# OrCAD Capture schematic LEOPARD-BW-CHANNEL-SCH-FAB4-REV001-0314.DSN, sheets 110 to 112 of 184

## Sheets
110 061_DDR4 DIMM CPU1 CHE-2: size A3; title: DDR4 DIMM CPU1 CHE-2
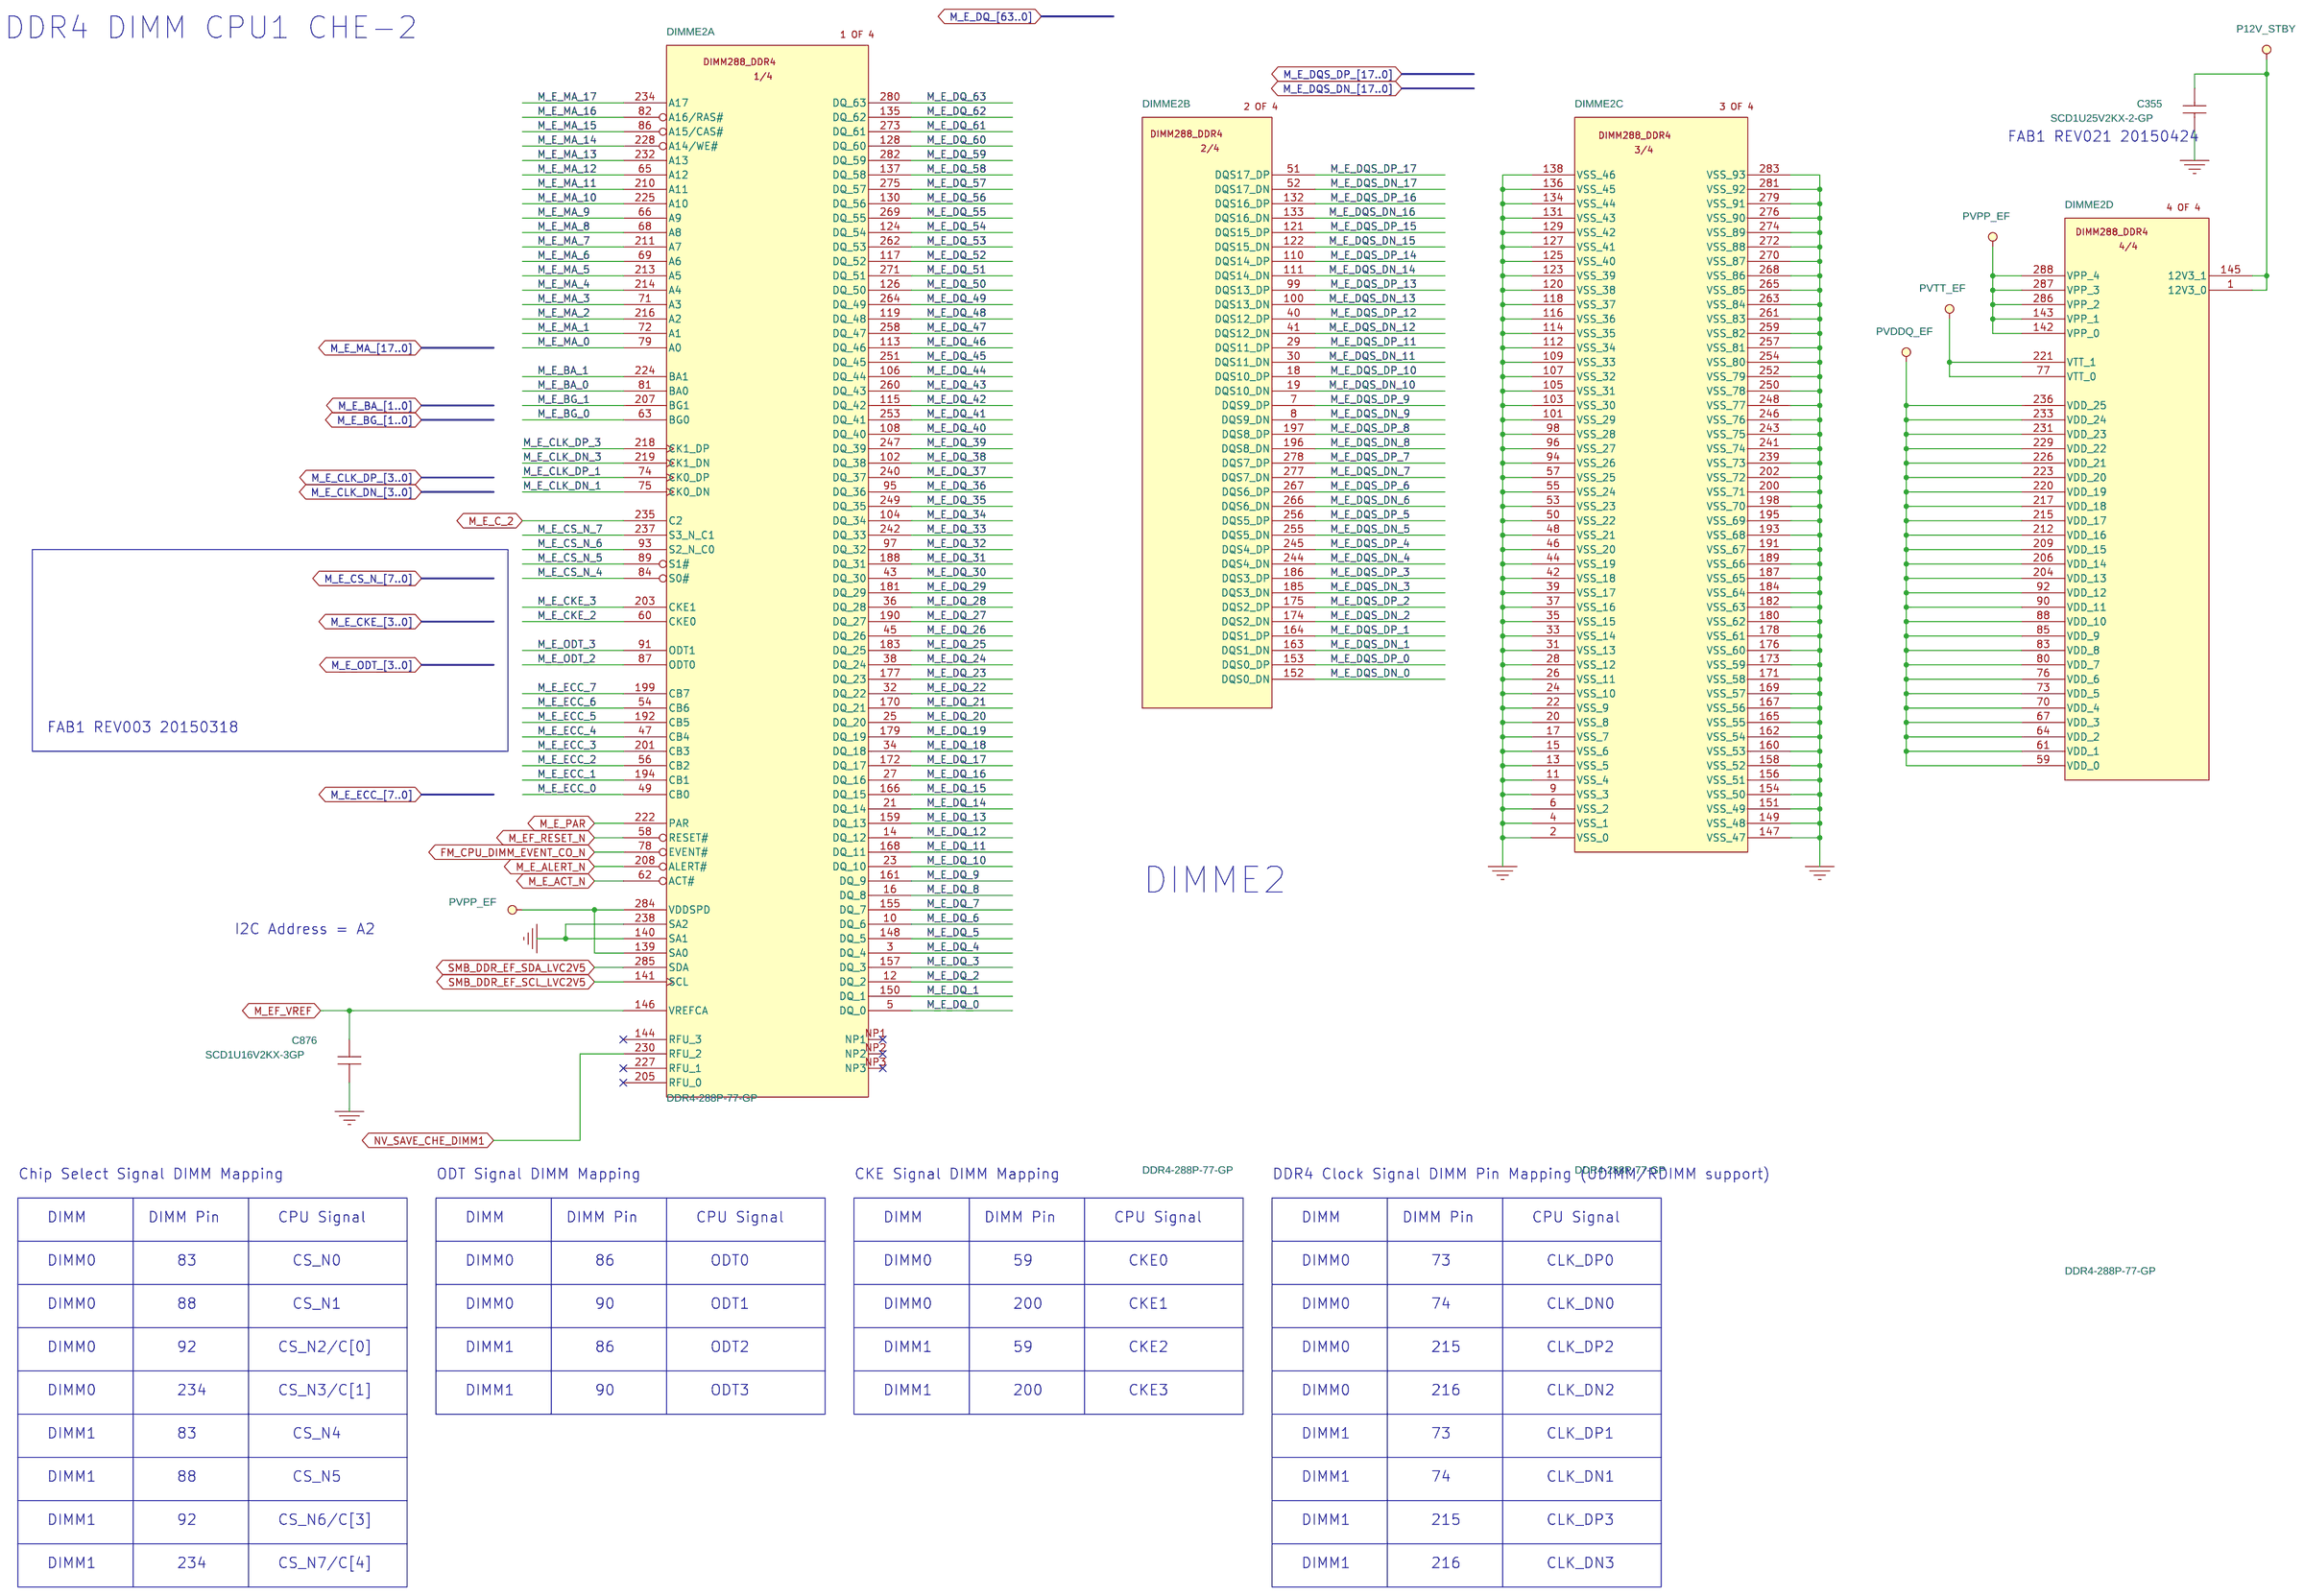
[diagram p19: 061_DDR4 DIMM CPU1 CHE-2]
111 060_DDR4 DIMM CPU1 CHE-1: size A3; title: DDR4 DIMM CPU1 CHE-1
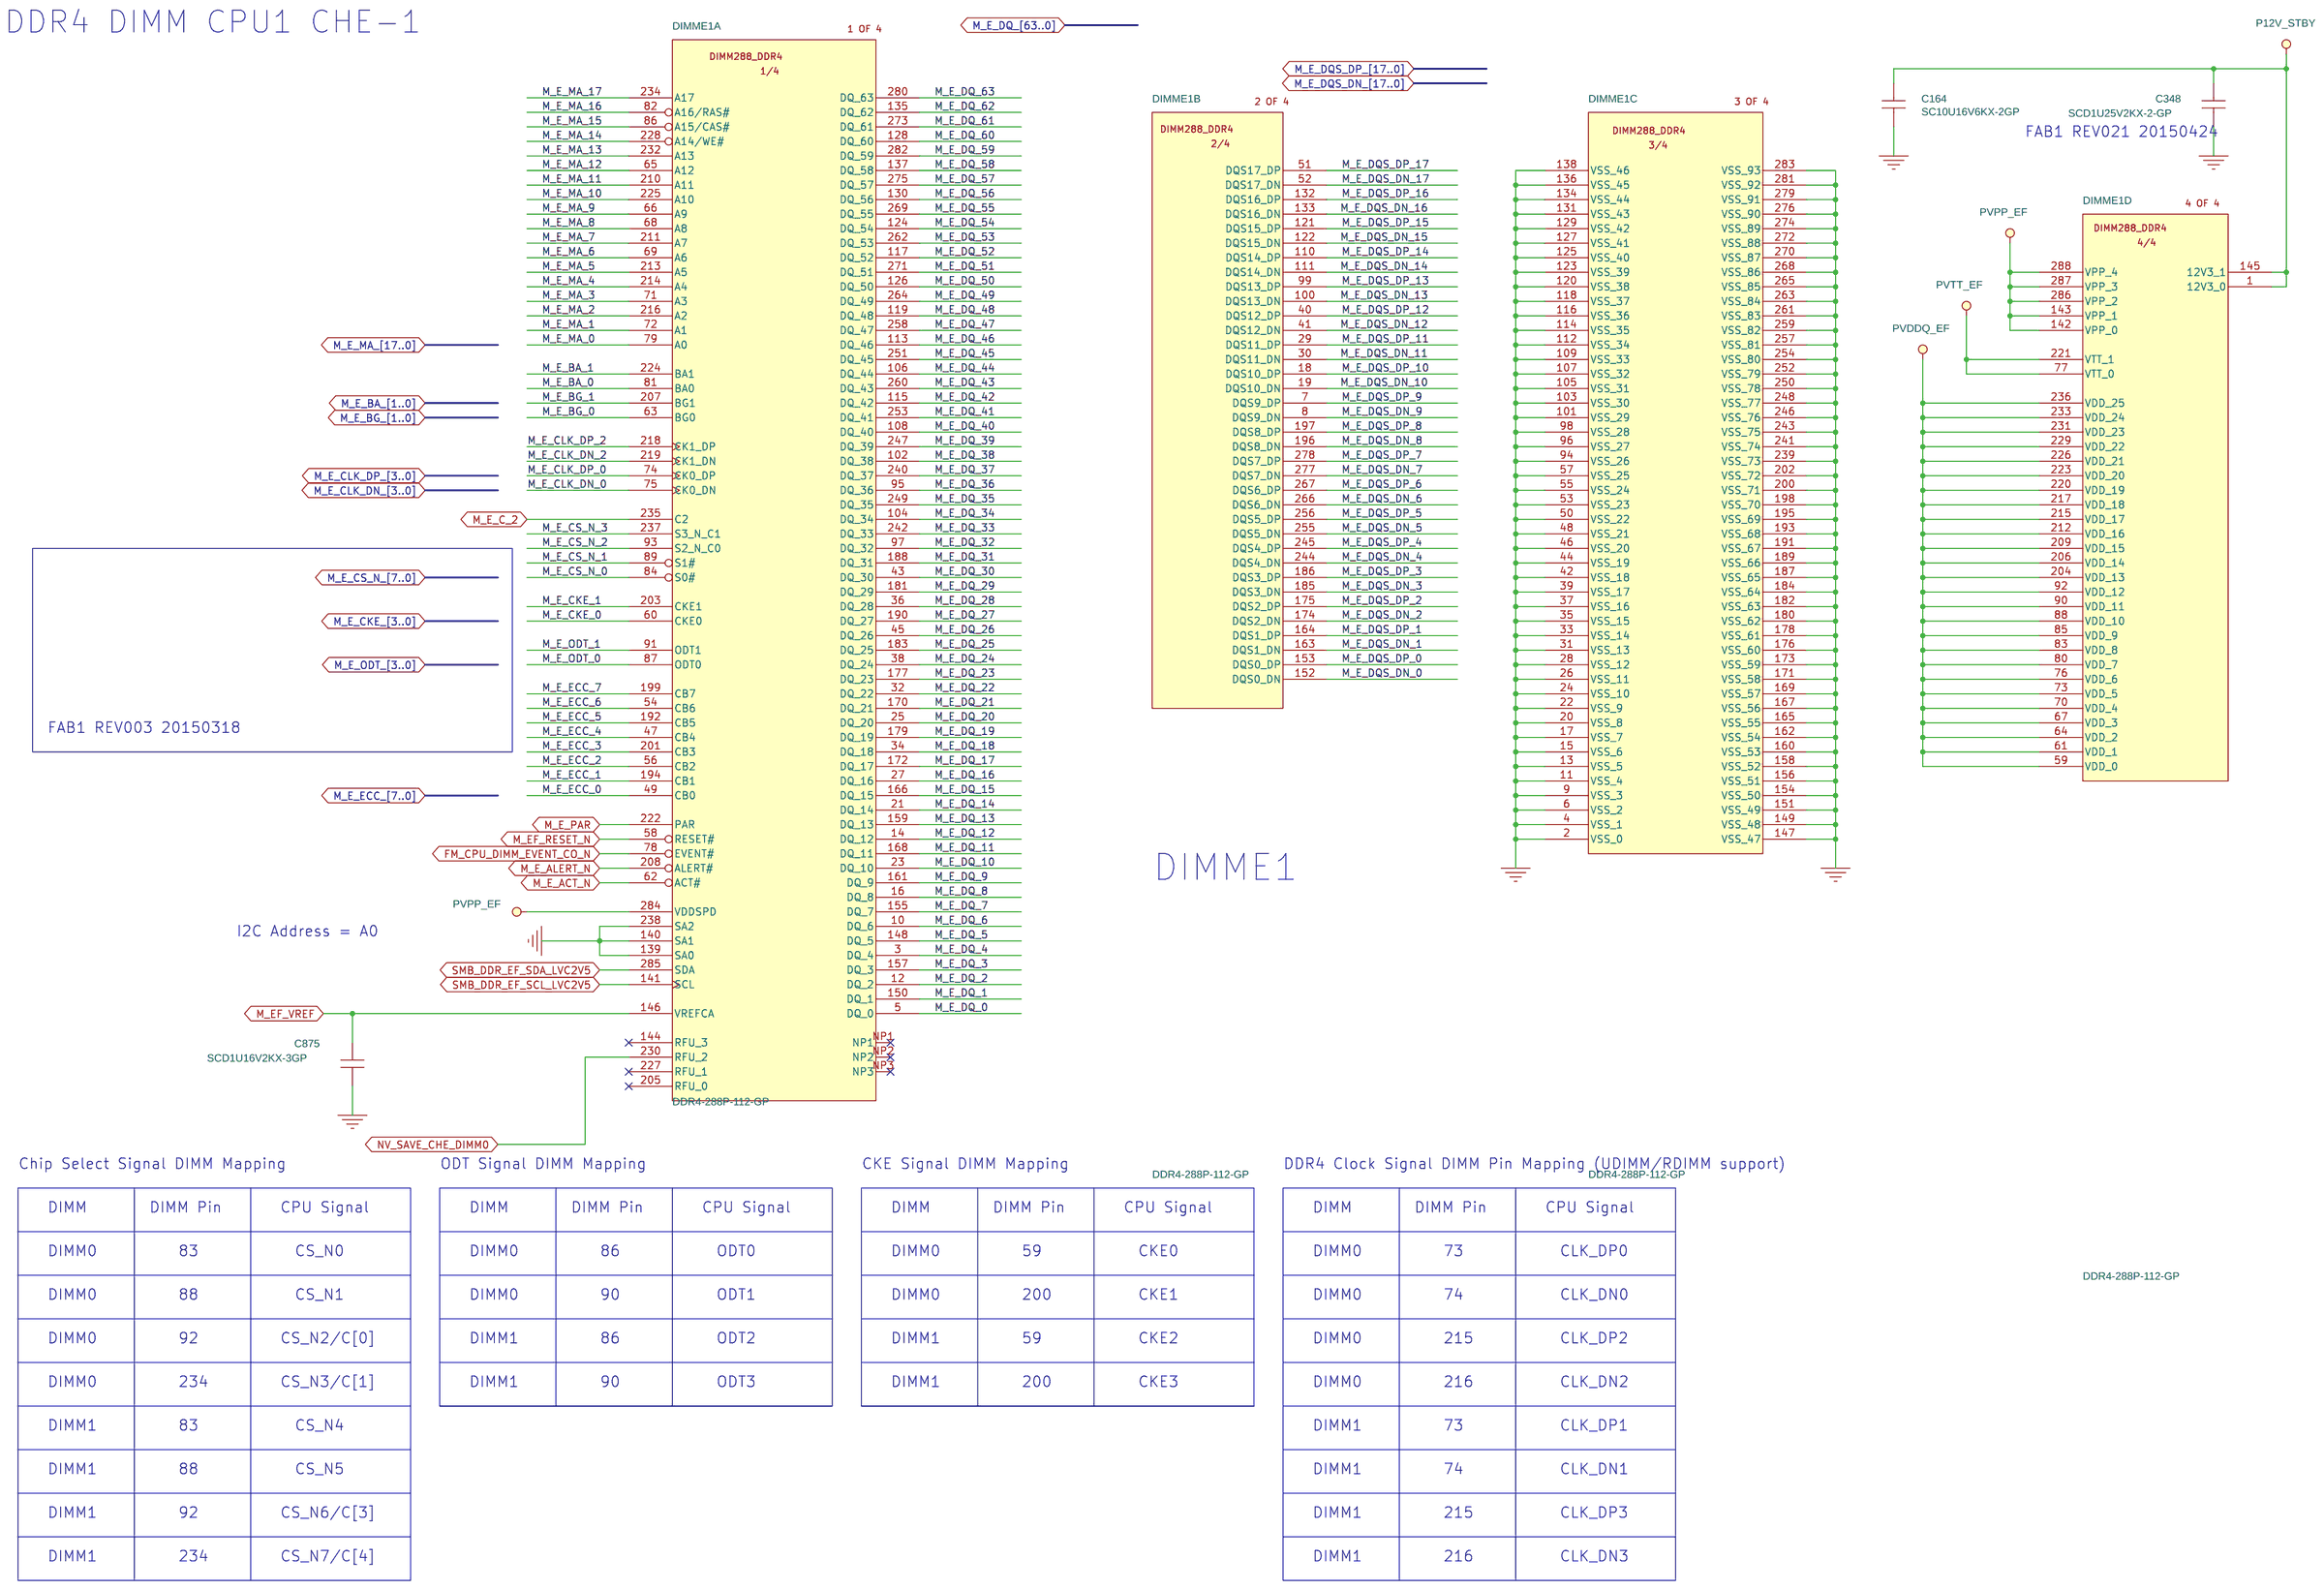
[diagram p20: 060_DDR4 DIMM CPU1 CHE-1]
112 059_DDR4 DIMM CPU0 CHD-2: size A3; title: DDR4 DIMM CPU0 CHD-2
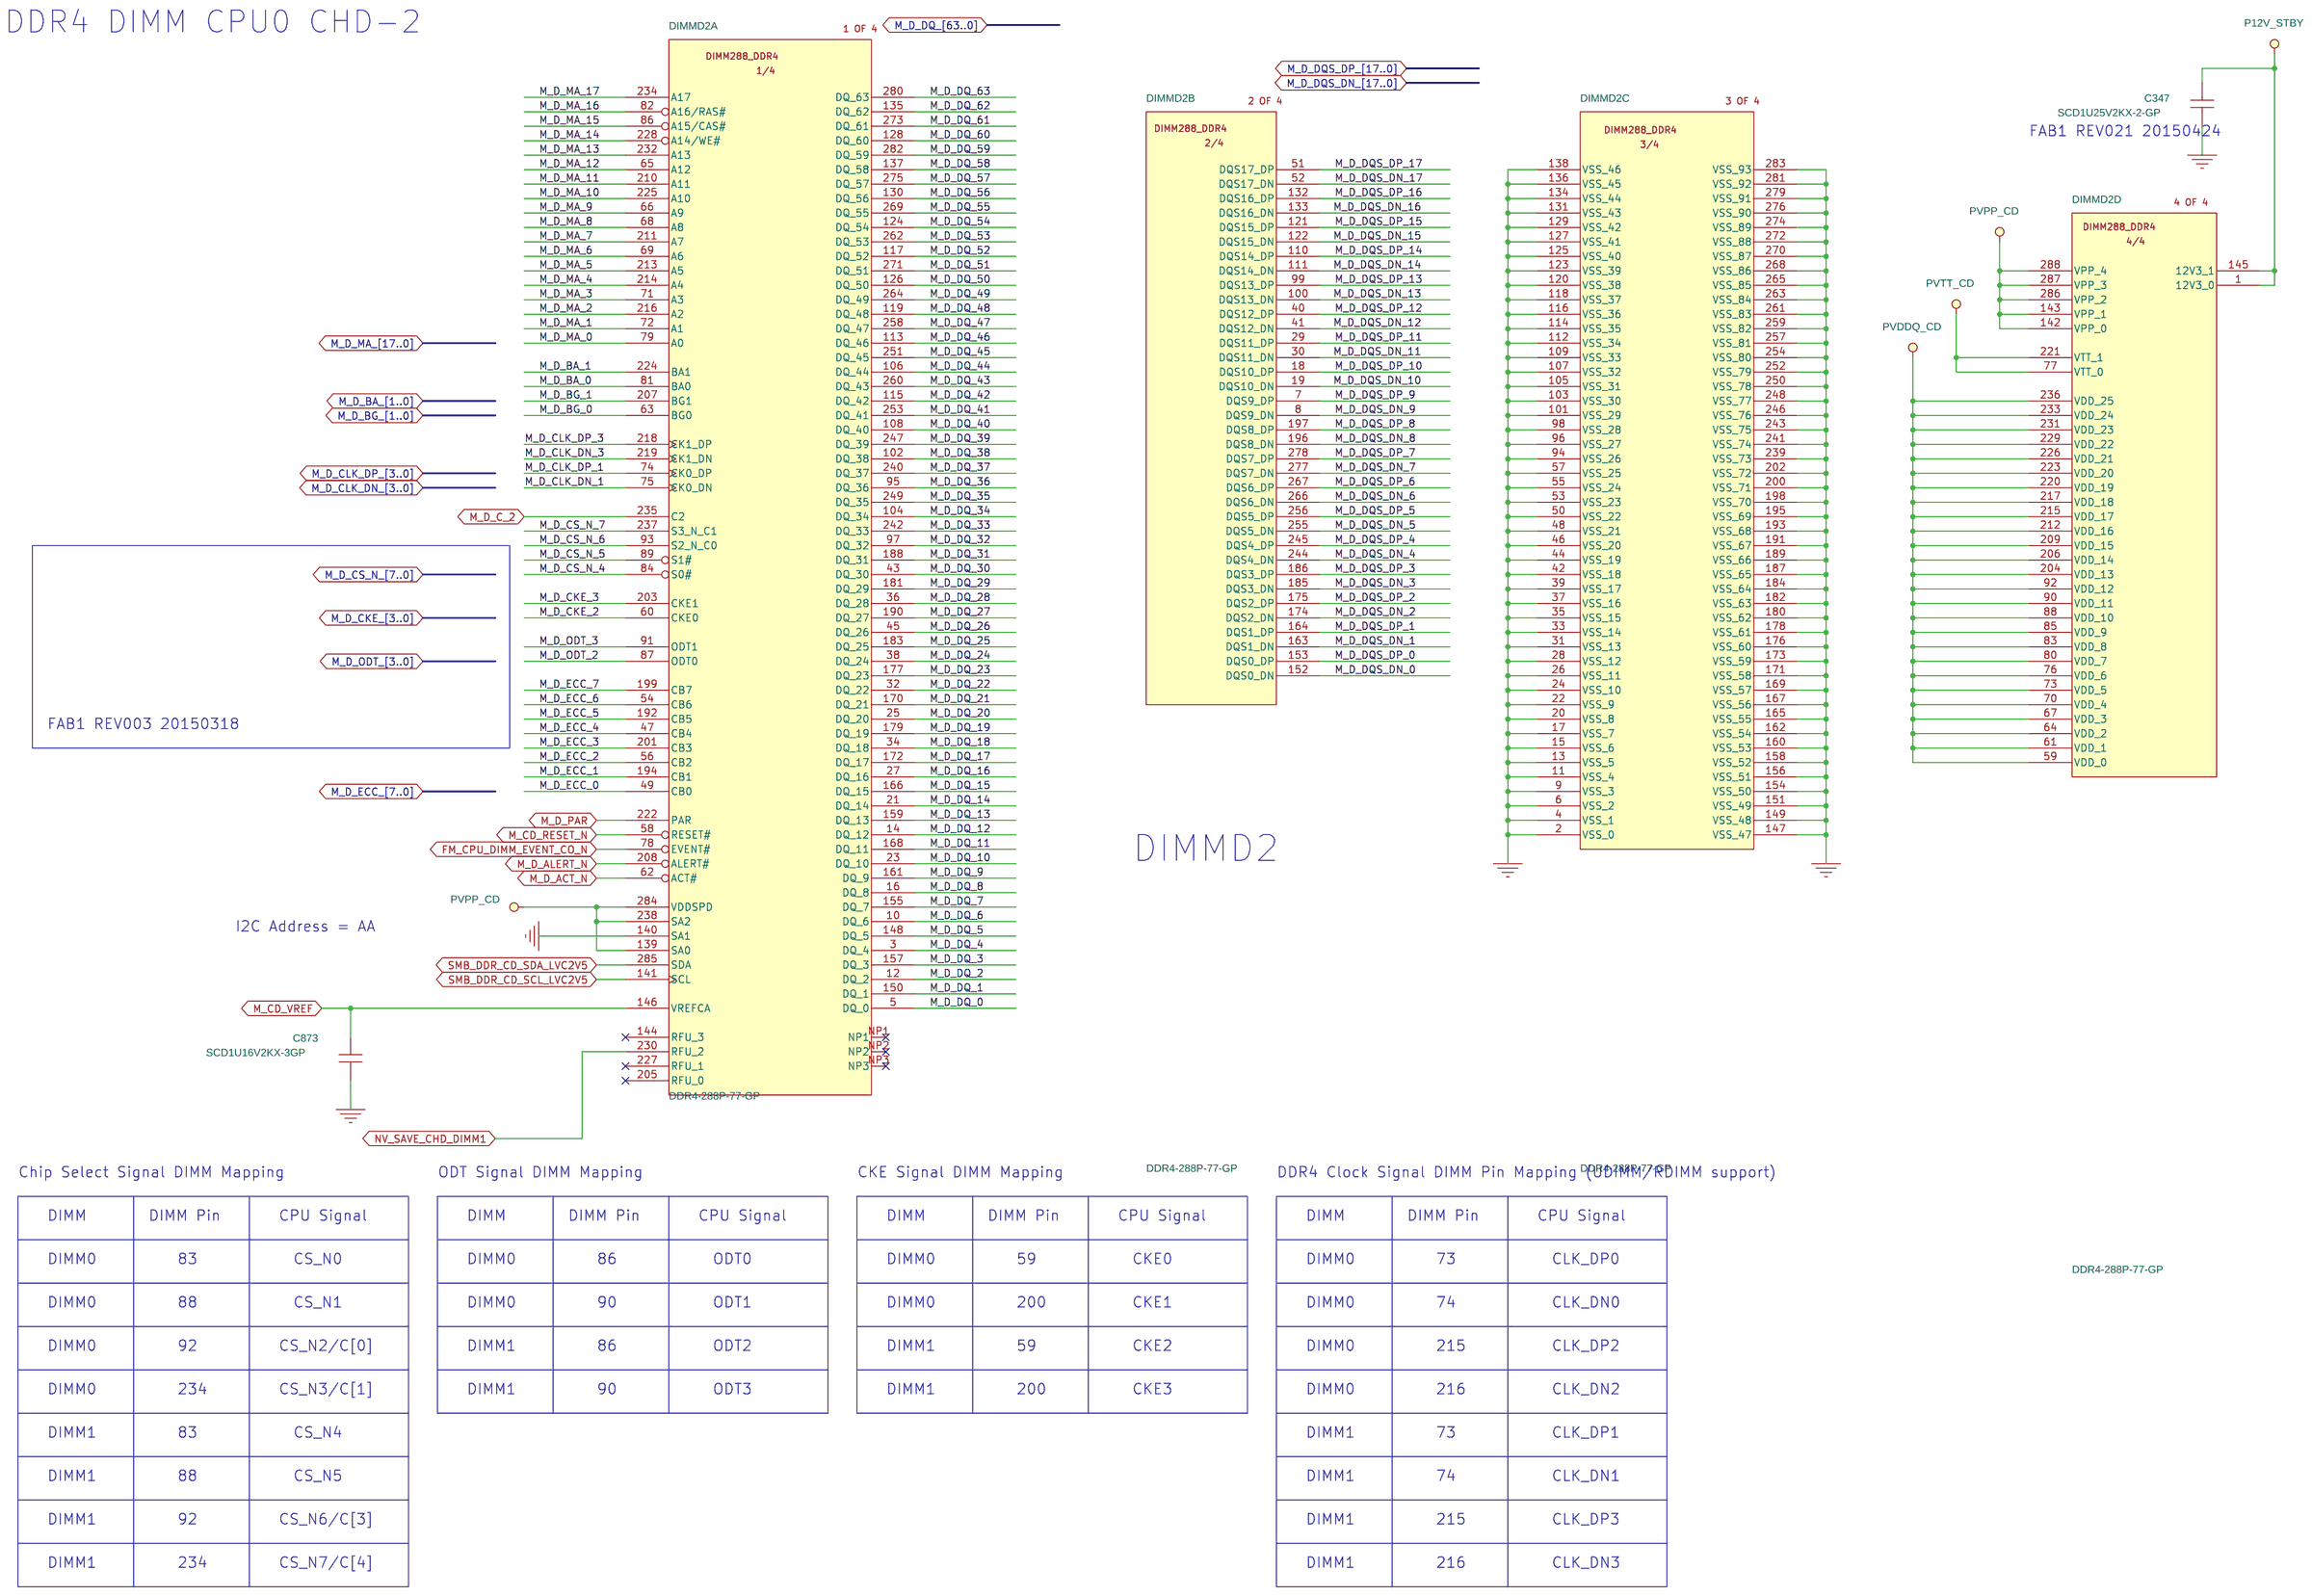
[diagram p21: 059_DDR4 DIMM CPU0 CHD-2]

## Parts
sheet 059_DDR4 DIMM CPU0 CHD-2
C347  SCD1U25V2KX-2-GP  [C402H22]
C873  SCD1U16V2KX-3GP  [C402H22]
DIMMD2  DDR4-288P-77-GP  [10124632-0001113LF]  (sections A,B,C,D)
sheet 060_DDR4 DIMM CPU1 CHE-1
C164  SC10U16V6KX-2GP  [C1206H71]
C348  SCD1U25V2KX-2-GP  [C402H22]
C875  SCD1U16V2KX-3GP  [C402H22]
DIMME1  DDR4-288P-112-GP  [10124632-0001113LF]  (sections A,B,C,D)
sheet 061_DDR4 DIMM CPU1 CHE-2
C355  SCD1U25V2KX-2-GP  [C402H22]
C876  SCD1U16V2KX-3GP  [C402H22]
DIMME2  DDR4-288P-77-GP  [10124632-0001113LF]  (sections A,B,C,D)

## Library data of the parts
C347 C348 C355 = SCD1U25V2KX-2-GP: CHIP CAP C 0.1U 25V K0402 X7R; GREENDFACTOR: R2_SA;HF_SA;G_SA;; Part Number: 78.10422.2FL; Part Type: SMD-BCG4; SPEC: http://wpqssvr.wistron.com.tw:7001/wpqs/servlet/COM.qpart.Attachment?PartNumber=78.10422.2FL
C873 C875 C876 = SCD1U16V2KX-3GP: CHIP CAP C 0.1U 16V K0402 X7R; CATEGORIES: CAP_1.xV; GREENDFACTOR: R2_SA;HF_SA;G_SA;; MAIN_SOURCE: M; Part Number: 78.10421.2FL; Part Type: SMD-BCG; SPEC: http://wpqssvr.wistron.com.tw:7001/wpqs/servlet/COM.qpart.Attachment?PartNumber=78.10421.2FL
DIMMD2 DIMME2 = DDR4-288P-77-GP: SKT DIMM DDR4 288P 10124632-0001001LF; GREENDFACTOR: R2_SA;; POP?: 022.10010.0B11; Part Number: 22.10244.1A1; Part Type: SOCKET-G1; SPEC: http://wpqssvr.wistron.com.tw:7001/wpqs/servlet/COM.qpart.Attachment?PartNumber=22.10244.1A1
C164 = SC10U16V6KX-2GP: CHIP CAP C 10U 16V K1206 X7R; GREENDFACTOR: R2_SA;HF_SA;G_SA;; Part Number: 78.10621.22L; Part Type: SMD-BCG; SPEC: http://wpqssvr.wistron.com.tw:7001/wpqs/servlet/COM.qpart.Attachment?PartNumber=78.10621.22L
DIMME1 = DDR4-288P-112-GP: SKT DIMM DDR4 288P 10124632-0003001LF; GREENDFACTOR: R2_C;; POP?: 022.10010.0E11; Part Number: 022.10010.0B91; Part Type: SOCKET-G2; SPEC: http://wpqssvr.wistron.com.tw:7001/wpqs/servlet/COM.qpart.Attachment?PartNumber=022.10010.0B91

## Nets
GND: C164.2 C347.2 C348.2 C355.2 C873.2 C875.2 C876.2 DIMMD2.2(VSS_0) DIMMD2.4(VSS_1) DIMMD2.6(VSS_2) DIMMD2.9(VSS_3) DIMMD2.11(VSS_4) DIMMD2.13(VSS_5) DIMMD2.15(VSS_6) DIMMD2.17(VSS_7) DIMMD2.20(VSS_8) DIMMD2.22(VSS_9) DIMMD2.24(VSS_10) DIMMD2.26(VSS_11) DIMMD2.28(VSS_12) DIMMD2.31(VSS_13) DIMMD2.33(VSS_14) DIMMD2.35(VSS_15) DIMMD2.37(VSS_16) DIMMD2.39(VSS_17) DIMMD2.42(VSS_18) DIMMD2.44(VSS_19) DIMMD2.46(VSS_20) DIMMD2.48(VSS_21) DIMMD2.50(VSS_22) DIMMD2.53(VSS_23) DIMMD2.55(VSS_24) DIMMD2.57(VSS_25) DIMMD2.94(VSS_26) DIMMD2.96(VSS_27) DIMMD2.98(VSS_28) DIMMD2.101(VSS_29) DIMMD2.103(VSS_30) DIMMD2.105(VSS_31) DIMMD2.107(VSS_32) DIMMD2.109(VSS_33) DIMMD2.112(VSS_34) DIMMD2.114(VSS_35) DIMMD2.116(VSS_36) DIMMD2.118(VSS_37) DIMMD2.120(VSS_38) DIMMD2.123(VSS_39) DIMMD2.125(VSS_40) DIMMD2.127(VSS_41) DIMMD2.129(VSS_42) DIMMD2.131(VSS_43) DIMMD2.134(VSS_44) DIMMD2.136(VSS_45) DIMMD2.138(VSS_46) DIMMD2.140(SA1) DIMMD2.147(VSS_47) DIMMD2.149(VSS_48) DIMMD2.151(VSS_49) DIMMD2.154(VSS_50) DIMMD2.156(VSS_51) DIMMD2.158(VSS_52) DIMMD2.160(VSS_53) DIMMD2.162(VSS_54) DIMMD2.165(VSS_55) DIMMD2.167(VSS_56) DIMMD2.169(VSS_57) DIMMD2.171(VSS_58) DIMMD2.173(VSS_59) DIMMD2.176(VSS_60) DIMMD2.178(VSS_61) DIMMD2.180(VSS_62) DIMMD2.182(VSS_63) DIMMD2.184(VSS_64) DIMMD2.187(VSS_65) DIMMD2.189(VSS_66) DIMMD2.191(VSS_67) DIMMD2.193(VSS_68) DIMMD2.195(VSS_69) DIMMD2.198(VSS_70) DIMMD2.200(VSS_71) DIMMD2.202(VSS_72) DIMMD2.239(VSS_73) DIMMD2.241(VSS_74) DIMMD2.243(VSS_75) DIMMD2.246(VSS_76) DIMMD2.248(VSS_77) DIMMD2.250(VSS_78) DIMMD2.252(VSS_79) DIMMD2.254(VSS_80) DIMMD2.257(VSS_81) DIMMD2.259(VSS_82) DIMMD2.261(VSS_83) DIMMD2.263(VSS_84) DIMMD2.265(VSS_85) DIMMD2.268(VSS_86) DIMMD2.270(VSS_87) DIMMD2.272(VSS_88) DIMMD2.274(VSS_89) DIMMD2.276(VSS_90) DIMMD2.279(VSS_91) DIMMD2.281(VSS_92) DIMMD2.283(VSS_93) DIMME1.2(VSS_0) DIMME1.4(VSS_1) DIMME1.6(VSS_2) DIMME1.9(VSS_3) DIMME1.11(VSS_4) DIMME1.13(VSS_5) DIMME1.15(VSS_6) DIMME1.17(VSS_7) DIMME1.20(VSS_8) DIMME1.22(VSS_9) DIMME1.24(VSS_10) DIMME1.26(VSS_11) DIMME1.28(VSS_12) DIMME1.31(VSS_13) DIMME1.33(VSS_14) DIMME1.35(VSS_15) DIMME1.37(VSS_16) DIMME1.39(VSS_17) DIMME1.42(VSS_18) DIMME1.44(VSS_19) DIMME1.46(VSS_20) DIMME1.48(VSS_21) DIMME1.50(VSS_22) DIMME1.53(VSS_23) DIMME1.55(VSS_24) DIMME1.57(VSS_25) DIMME1.94(VSS_26) DIMME1.96(VSS_27) DIMME1.98(VSS_28) DIMME1.101(VSS_29) DIMME1.103(VSS_30) DIMME1.105(VSS_31) DIMME1.107(VSS_32) DIMME1.109(VSS_33) DIMME1.112(VSS_34) DIMME1.114(VSS_35) DIMME1.116(VSS_36) DIMME1.118(VSS_37) DIMME1.120(VSS_38) DIMME1.123(VSS_39) DIMME1.125(VSS_40) DIMME1.127(VSS_41) DIMME1.129(VSS_42) DIMME1.131(VSS_43) DIMME1.134(VSS_44) DIMME1.136(VSS_45) DIMME1.138(VSS_46) DIMME1.139(SA0) DIMME1.140(SA1) DIMME1.147(VSS_47) DIMME1.149(VSS_48) DIMME1.151(VSS_49) DIMME1.154(VSS_50) DIMME1.156(VSS_51) DIMME1.158(VSS_52) DIMME1.160(VSS_53) DIMME1.162(VSS_54) DIMME1.165(VSS_55) DIMME1.167(VSS_56) DIMME1.169(VSS_57) DIMME1.171(VSS_58) DIMME1.173(VSS_59) DIMME1.176(VSS_60) DIMME1.178(VSS_61) DIMME1.180(VSS_62) DIMME1.182(VSS_63) DIMME1.184(VSS_64) DIMME1.187(VSS_65) DIMME1.189(VSS_66) DIMME1.191(VSS_67) DIMME1.193(VSS_68) DIMME1.195(VSS_69) DIMME1.198(VSS_70) DIMME1.200(VSS_71) DIMME1.202(VSS_72) DIMME1.238(SA2) DIMME1.239(VSS_73) DIMME1.241(VSS_74) DIMME1.243(VSS_75) DIMME1.246(VSS_76) DIMME1.248(VSS_77) DIMME1.250(VSS_78) DIMME1.252(VSS_79) DIMME1.254(VSS_80) DIMME1.257(VSS_81) DIMME1.259(VSS_82) DIMME1.261(VSS_83) DIMME1.263(VSS_84) DIMME1.265(VSS_85) DIMME1.268(VSS_86) DIMME1.270(VSS_87) DIMME1.272(VSS_88) DIMME1.274(VSS_89) DIMME1.276(VSS_90) DIMME1.279(VSS_91) DIMME1.281(VSS_92) DIMME1.283(VSS_93) DIMME2.2(VSS_0) DIMME2.4(VSS_1) DIMME2.6(VSS_2) DIMME2.9(VSS_3) DIMME2.11(VSS_4) DIMME2.13(VSS_5) DIMME2.15(VSS_6) DIMME2.17(VSS_7) DIMME2.20(VSS_8) DIMME2.22(VSS_9) DIMME2.24(VSS_10) DIMME2.26(VSS_11) DIMME2.28(VSS_12) DIMME2.31(VSS_13) DIMME2.33(VSS_14) DIMME2.35(VSS_15) DIMME2.37(VSS_16) DIMME2.39(VSS_17) DIMME2.42(VSS_18) DIMME2.44(VSS_19) DIMME2.46(VSS_20) DIMME2.48(VSS_21) DIMME2.50(VSS_22) DIMME2.53(VSS_23) DIMME2.55(VSS_24) DIMME2.57(VSS_25) DIMME2.94(VSS_26) DIMME2.96(VSS_27) DIMME2.98(VSS_28) DIMME2.101(VSS_29) DIMME2.103(VSS_30) DIMME2.105(VSS_31) DIMME2.107(VSS_32) DIMME2.109(VSS_33) DIMME2.112(VSS_34) DIMME2.114(VSS_35) DIMME2.116(VSS_36) DIMME2.118(VSS_37) DIMME2.120(VSS_38) DIMME2.123(VSS_39) DIMME2.125(VSS_40) DIMME2.127(VSS_41) DIMME2.129(VSS_42) DIMME2.131(VSS_43) DIMME2.134(VSS_44) DIMME2.136(VSS_45) DIMME2.138(VSS_46) DIMME2.140(SA1) DIMME2.147(VSS_47) DIMME2.149(VSS_48) DIMME2.151(VSS_49) DIMME2.154(VSS_50) DIMME2.156(VSS_51) DIMME2.158(VSS_52) DIMME2.160(VSS_53) DIMME2.162(VSS_54) DIMME2.165(VSS_55) DIMME2.167(VSS_56) DIMME2.169(VSS_57) DIMME2.171(VSS_58) DIMME2.173(VSS_59) DIMME2.176(VSS_60) DIMME2.178(VSS_61) DIMME2.180(VSS_62) DIMME2.182(VSS_63) DIMME2.184(VSS_64) DIMME2.187(VSS_65) DIMME2.189(VSS_66) DIMME2.191(VSS_67) DIMME2.193(VSS_68) DIMME2.195(VSS_69) DIMME2.198(VSS_70) DIMME2.200(VSS_71) DIMME2.202(VSS_72) DIMME2.238(SA2) DIMME2.239(VSS_73) DIMME2.241(VSS_74) DIMME2.243(VSS_75) DIMME2.246(VSS_76) DIMME2.248(VSS_77) DIMME2.250(VSS_78) DIMME2.252(VSS_79) DIMME2.254(VSS_80) DIMME2.257(VSS_81) DIMME2.259(VSS_82) DIMME2.261(VSS_83) DIMME2.263(VSS_84) DIMME2.265(VSS_85) DIMME2.268(VSS_86) DIMME2.270(VSS_87) DIMME2.272(VSS_88) DIMME2.274(VSS_89) DIMME2.276(VSS_90) DIMME2.279(VSS_91) DIMME2.281(VSS_92) DIMME2.283(VSS_93) ; also on sheet 1 2 3 4 5 6 7 8 9 10 11 12 13 14 15 16 17 18 19 20 21 22 23 24 25 26 27 28 29 30 31 32 33 34 35 36 37 38 39 44 46 47 49 50 51 52 53 54 55 56 57 58 59 60 61 62 63 64 65 66 69 70 71 73 74 75 76 78 79 80 81 82 83 84 86 87 88 89 90 91 92 93 94 95 96 97 98 99 100 101 102 103 104 105 106 107 108 109 113 114 115 116 117 118 119 128 129 138 139 159 160 161 166 168 169 170 171 172 173 174 175 176 177 180 181 182 183 184
P12V_STBY: C164.1 C347.1 C348.1 C355.1 DIMMD2.1(12V3_0) DIMMD2.145(12V3_1) DIMME1.1(12V3_0) DIMME1.145(12V3_1) DIMME2.1(12V3_0) DIMME2.145(12V3_1) ; also on sheet 2 3 4 7 9 10 11 12 13 17 18 22 23 27 28 32 36 59 60 75 95 104 105 106 107 108 109 113 114 115 116 117 118 119
PVDDQ_CD: DIMMD2.59(VDD_0) DIMMD2.61(VDD_1) DIMMD2.64(VDD_2) DIMMD2.67(VDD_3) DIMMD2.70(VDD_4) DIMMD2.73(VDD_5) DIMMD2.76(VDD_6) DIMMD2.80(VDD_7) DIMMD2.83(VDD_8) DIMMD2.85(VDD_9) DIMMD2.88(VDD_10) DIMMD2.90(VDD_11) DIMMD2.92(VDD_12) DIMMD2.204(VDD_13) DIMMD2.206(VDD_14) DIMMD2.209(VDD_15) DIMMD2.212(VDD_16) DIMMD2.215(VDD_17) DIMMD2.217(VDD_18) DIMMD2.220(VDD_19) DIMMD2.223(VDD_20) DIMMD2.226(VDD_21) DIMMD2.229(VDD_22) DIMMD2.231(VDD_23) DIMMD2.233(VDD_24) DIMMD2.236(VDD_25) ; also on sheet 23 25 45 97 113 114 115 130 139
PVDDQ_EF: DIMME1.59(VDD_0) DIMME1.61(VDD_1) DIMME1.64(VDD_2) DIMME1.67(VDD_3) DIMME1.70(VDD_4) DIMME1.73(VDD_5) DIMME1.76(VDD_6) DIMME1.80(VDD_7) DIMME1.83(VDD_8) DIMME1.85(VDD_9) DIMME1.88(VDD_10) DIMME1.90(VDD_11) DIMME1.92(VDD_12) DIMME1.204(VDD_13) DIMME1.206(VDD_14) DIMME1.209(VDD_15) DIMME1.212(VDD_16) DIMME1.215(VDD_17) DIMME1.217(VDD_18) DIMME1.220(VDD_19) DIMME1.223(VDD_20) DIMME1.226(VDD_21) DIMME1.229(VDD_22) DIMME1.231(VDD_23) DIMME1.233(VDD_24) DIMME1.236(VDD_25) DIMME2.59(VDD_0) DIMME2.61(VDD_1) DIMME2.64(VDD_2) DIMME2.67(VDD_3) DIMME2.70(VDD_4) DIMME2.73(VDD_5) DIMME2.76(VDD_6) DIMME2.80(VDD_7) DIMME2.83(VDD_8) DIMME2.85(VDD_9) DIMME2.88(VDD_10) DIMME2.90(VDD_11) DIMME2.92(VDD_12) DIMME2.204(VDD_13) DIMME2.206(VDD_14) DIMME2.209(VDD_15) DIMME2.212(VDD_16) DIMME2.215(VDD_17) DIMME2.217(VDD_18) DIMME2.220(VDD_19) DIMME2.223(VDD_20) DIMME2.226(VDD_21) DIMME2.229(VDD_22) DIMME2.231(VDD_23) DIMME2.233(VDD_24) DIMME2.236(VDD_25) ; also on sheet 18 20 45 97 108 109 120 129
FM_CPU_DIMM_EVENT_CO_N: DIMMD2.78(EVENT#) DIMME1.78(EVENT#) DIMME2.78(EVENT#) ; also on sheet 98 104 105 106 107 108 109 113 114 115 116 117 118 119
M_CD_RESET_N: DIMMD2.58(RESET#) ; also on sheet 113 114 115 139
M_CD_VREF: C873.1 DIMMD2.146(VREFCA) ; also on sheet 113 114 115 139
M_D_ACT_N: DIMMD2.62(ACT#) ; also on sheet 113 134
M_D_ALERT_N: DIMMD2.208(ALERT#) ; also on sheet 113 134
M_D_BA_0: DIMMD2.81(BA0) ; also on sheet 113 134
M_D_BA_1: DIMMD2.224(BA1) ; also on sheet 113 134
M_D_BG_0: DIMMD2.63(BG0) ; also on sheet 113 134
M_D_BG_1: DIMMD2.207(BG1) ; also on sheet 113 134
M_D_C_2: DIMMD2.235(C2) ; also on sheet 113 134
M_D_CKE_2: DIMMD2.60(CKE0) ; also on sheet 134
M_D_CKE_3: DIMMD2.203(CKE1) ; also on sheet 134
M_D_CLK_DN_1: DIMMD2.75(CK0_DN) ; also on sheet 134
M_D_CLK_DN_3: DIMMD2.219(CK1_DN) ; also on sheet 134
M_D_CLK_DP_1: DIMMD2.74(CK0_DP) ; also on sheet 134
M_D_CLK_DP_3: DIMMD2.218(CK1_DP) ; also on sheet 134
M_D_CS_N_4: DIMMD2.84(S0#) ; also on sheet 134
M_D_CS_N_5: DIMMD2.89(S1#) ; also on sheet 134
M_D_CS_N_6: DIMMD2.93(S2_N_C0) ; also on sheet 134
M_D_CS_N_7: DIMMD2.237(S3_N_C1) ; also on sheet 134
M_D_DQ_0: DIMMD2.5(DQ_0) ; also on sheet 113 134
M_D_DQ_1: DIMMD2.150(DQ_1) ; also on sheet 113 134
M_D_DQ_2: DIMMD2.12(DQ_2) ; also on sheet 113 134
M_D_DQ_3: DIMMD2.157(DQ_3) ; also on sheet 113 134
M_D_DQ_4: DIMMD2.3(DQ_4) ; also on sheet 113 134
M_D_DQ_5: DIMMD2.148(DQ_5) ; also on sheet 113 134
M_D_DQ_6: DIMMD2.10(DQ_6) ; also on sheet 113 134
M_D_DQ_7: DIMMD2.155(DQ_7) ; also on sheet 113 134
M_D_DQ_8: DIMMD2.16(DQ_8) ; also on sheet 113 134
M_D_DQ_9: DIMMD2.161(DQ_9) ; also on sheet 113 134
M_D_DQ_10: DIMMD2.23(DQ_10) ; also on sheet 113 134
M_D_DQ_11: DIMMD2.168(DQ_11) ; also on sheet 113 134
M_D_DQ_12: DIMMD2.14(DQ_12) ; also on sheet 113 134
M_D_DQ_13: DIMMD2.159(DQ_13) ; also on sheet 113 134
M_D_DQ_14: DIMMD2.21(DQ_14) ; also on sheet 113 134
M_D_DQ_15: DIMMD2.166(DQ_15) ; also on sheet 113 134
M_D_DQ_16: DIMMD2.27(DQ_16) ; also on sheet 113 134
M_D_DQ_17: DIMMD2.172(DQ_17) ; also on sheet 113 134
M_D_DQ_18: DIMMD2.34(DQ_18) ; also on sheet 113 134
M_D_DQ_19: DIMMD2.179(DQ_19) ; also on sheet 113 134
M_D_DQ_20: DIMMD2.25(DQ_20) ; also on sheet 113 134
M_D_DQ_21: DIMMD2.170(DQ_21) ; also on sheet 113 134
M_D_DQ_22: DIMMD2.32(DQ_22) ; also on sheet 113 134
M_D_DQ_23: DIMMD2.177(DQ_23) ; also on sheet 113 134
M_D_DQ_24: DIMMD2.38(DQ_24) ; also on sheet 113 134
M_D_DQ_25: DIMMD2.183(DQ_25) ; also on sheet 113 134
M_D_DQ_26: DIMMD2.45(DQ_26) ; also on sheet 113 134
M_D_DQ_27: DIMMD2.190(DQ_27) ; also on sheet 113 134
M_D_DQ_28: DIMMD2.36(DQ_28) ; also on sheet 113 134
M_D_DQ_29: DIMMD2.181(DQ_29) ; also on sheet 113 134
M_D_DQ_30: DIMMD2.43(DQ_30) ; also on sheet 113 134
M_D_DQ_31: DIMMD2.188(DQ_31) ; also on sheet 113 134
M_D_DQ_32: DIMMD2.97(DQ_32) ; also on sheet 113 134
M_D_DQ_33: DIMMD2.242(DQ_33) ; also on sheet 113 134
M_D_DQ_34: DIMMD2.104(DQ_34) ; also on sheet 113 134
M_D_DQ_35: DIMMD2.249(DQ_35) ; also on sheet 113 134
M_D_DQ_36: DIMMD2.95(DQ_36) ; also on sheet 113 134
M_D_DQ_37: DIMMD2.240(DQ_37) ; also on sheet 113 134
M_D_DQ_38: DIMMD2.102(DQ_38) ; also on sheet 113 134
M_D_DQ_39: DIMMD2.247(DQ_39) ; also on sheet 113 134
M_D_DQ_40: DIMMD2.108(DQ_40) ; also on sheet 113 134
M_D_DQ_41: DIMMD2.253(DQ_41) ; also on sheet 113 134
M_D_DQ_42: DIMMD2.115(DQ_42) ; also on sheet 113 134
M_D_DQ_43: DIMMD2.260(DQ_43) ; also on sheet 113 134
M_D_DQ_44: DIMMD2.106(DQ_44) ; also on sheet 113 134
M_D_DQ_45: DIMMD2.251(DQ_45) ; also on sheet 113 134
M_D_DQ_46: DIMMD2.113(DQ_46) ; also on sheet 113 134
M_D_DQ_47: DIMMD2.258(DQ_47) ; also on sheet 113 134
M_D_DQ_48: DIMMD2.119(DQ_48) ; also on sheet 113 134
M_D_DQ_49: DIMMD2.264(DQ_49) ; also on sheet 113 134
M_D_DQ_50: DIMMD2.126(DQ_50) ; also on sheet 113 134
M_D_DQ_51: DIMMD2.271(DQ_51) ; also on sheet 113 134
M_D_DQ_52: DIMMD2.117(DQ_52) ; also on sheet 113 134
M_D_DQ_53: DIMMD2.262(DQ_53) ; also on sheet 113 134
M_D_DQ_54: DIMMD2.124(DQ_54) ; also on sheet 113 134
M_D_DQ_55: DIMMD2.269(DQ_55) ; also on sheet 113 134
M_D_DQ_56: DIMMD2.130(DQ_56) ; also on sheet 113 134
M_D_DQ_57: DIMMD2.275(DQ_57) ; also on sheet 113 134
M_D_DQ_58: DIMMD2.137(DQ_58) ; also on sheet 113 134
M_D_DQ_59: DIMMD2.282(DQ_59) ; also on sheet 113 134
M_D_DQ_60: DIMMD2.128(DQ_60) ; also on sheet 113 134
M_D_DQ_61: DIMMD2.273(DQ_61) ; also on sheet 113 134
M_D_DQ_62: DIMMD2.135(DQ_62) ; also on sheet 113 134
M_D_DQ_63: DIMMD2.280(DQ_63) ; also on sheet 113 134
M_D_DQS_DN_0: DIMMD2.152(DQS0_DN) ; also on sheet 113 134
M_D_DQS_DN_1: DIMMD2.163(DQS1_DN) ; also on sheet 113 134
M_D_DQS_DN_2: DIMMD2.174(DQS2_DN) ; also on sheet 113 134
M_D_DQS_DN_3: DIMMD2.185(DQS3_DN) ; also on sheet 113 134
M_D_DQS_DN_4: DIMMD2.244(DQS4_DN) ; also on sheet 113 134
M_D_DQS_DN_5: DIMMD2.255(DQS5_DN) ; also on sheet 113 134
M_D_DQS_DN_6: DIMMD2.266(DQS6_DN) ; also on sheet 113 134
M_D_DQS_DN_7: DIMMD2.277(DQS7_DN) ; also on sheet 113 134
M_D_DQS_DN_8: DIMMD2.196(DQS8_DN) ; also on sheet 113 134
M_D_DQS_DN_9: DIMMD2.8(DQS9_DN) ; also on sheet 113 134
M_D_DQS_DN_10: DIMMD2.19(DQS10_DN) ; also on sheet 113 134
M_D_DQS_DN_11: DIMMD2.30(DQS11_DN) ; also on sheet 113 134
M_D_DQS_DN_12: DIMMD2.41(DQS12_DN) ; also on sheet 113 134
M_D_DQS_DN_13: DIMMD2.100(DQS13_DN) ; also on sheet 113 134
M_D_DQS_DN_14: DIMMD2.111(DQS14_DN) ; also on sheet 113 134
M_D_DQS_DN_15: DIMMD2.122(DQS15_DN) ; also on sheet 113 134
M_D_DQS_DN_16: DIMMD2.133(DQS16_DN) ; also on sheet 113 134
M_D_DQS_DN_17: DIMMD2.52(DQS17_DN) ; also on sheet 113 134
M_D_DQS_DP_0: DIMMD2.153(DQS0_DP) ; also on sheet 113 134
M_D_DQS_DP_1: DIMMD2.164(DQS1_DP) ; also on sheet 113 134
M_D_DQS_DP_2: DIMMD2.175(DQS2_DP) ; also on sheet 113 134
M_D_DQS_DP_3: DIMMD2.186(DQS3_DP) ; also on sheet 113 134
M_D_DQS_DP_4: DIMMD2.245(DQS4_DP) ; also on sheet 113 134
M_D_DQS_DP_5: DIMMD2.256(DQS5_DP) ; also on sheet 113 134
M_D_DQS_DP_6: DIMMD2.267(DQS6_DP) ; also on sheet 113 134
M_D_DQS_DP_7: DIMMD2.278(DQS7_DP) ; also on sheet 113 134
M_D_DQS_DP_8: DIMMD2.197(DQS8_DP) ; also on sheet 113 134
M_D_DQS_DP_9: DIMMD2.7(DQS9_DP) ; also on sheet 113 134
M_D_DQS_DP_10: DIMMD2.18(DQS10_DP) ; also on sheet 113 134
M_D_DQS_DP_11: DIMMD2.29(DQS11_DP) ; also on sheet 113 134
M_D_DQS_DP_12: DIMMD2.40(DQS12_DP) ; also on sheet 113 134
M_D_DQS_DP_13: DIMMD2.99(DQS13_DP) ; also on sheet 113 134
M_D_DQS_DP_14: DIMMD2.110(DQS14_DP) ; also on sheet 113 134
M_D_DQS_DP_15: DIMMD2.121(DQS15_DP) ; also on sheet 113 134
M_D_DQS_DP_16: DIMMD2.132(DQS16_DP) ; also on sheet 113 134
M_D_DQS_DP_17: DIMMD2.51(DQS17_DP) ; also on sheet 113 134
M_D_ECC_0: DIMMD2.49(CB0) ; also on sheet 113 134
M_D_ECC_1: DIMMD2.194(CB1) ; also on sheet 113 134
M_D_ECC_2: DIMMD2.56(CB2) ; also on sheet 113 134
M_D_ECC_3: DIMMD2.201(CB3) ; also on sheet 113 134
M_D_ECC_4: DIMMD2.47(CB4) ; also on sheet 113 134
M_D_ECC_5: DIMMD2.192(CB5) ; also on sheet 113 134
M_D_ECC_6: DIMMD2.54(CB6) ; also on sheet 113 134
M_D_ECC_7: DIMMD2.199(CB7) ; also on sheet 113 134
M_D_MA_0: DIMMD2.79(A0) ; also on sheet 113 134
M_D_MA_1: DIMMD2.72(A1) ; also on sheet 113 134
M_D_MA_2: DIMMD2.216(A2) ; also on sheet 113 134
M_D_MA_3: DIMMD2.71(A3) ; also on sheet 113 134
M_D_MA_4: DIMMD2.214(A4) ; also on sheet 113 134
M_D_MA_5: DIMMD2.213(A5) ; also on sheet 113 134
M_D_MA_6: DIMMD2.69(A6) ; also on sheet 113 134
M_D_MA_7: DIMMD2.211(A7) ; also on sheet 113 134
M_D_MA_8: DIMMD2.68(A8) ; also on sheet 113 134
M_D_MA_9: DIMMD2.66(A9) ; also on sheet 113 134
M_D_MA_10: DIMMD2.225(A10) ; also on sheet 113 134
M_D_MA_11: DIMMD2.210(A11) ; also on sheet 113 134
M_D_MA_12: DIMMD2.65(A12) ; also on sheet 113 134
M_D_MA_13: DIMMD2.232(A13) ; also on sheet 113 134
M_D_MA_14: DIMMD2.228(A14/WE#) ; also on sheet 113 134
M_D_MA_15: DIMMD2.86(A15/CAS#) ; also on sheet 113 134
M_D_MA_16: DIMMD2.82(A16/RAS#) ; also on sheet 113 134
M_D_MA_17: DIMMD2.234(A17) ; also on sheet 113 134
M_D_ODT_2: DIMMD2.87(ODT0) ; also on sheet 134
M_D_ODT_3: DIMMD2.91(ODT1) ; also on sheet 134
M_D_PAR: DIMMD2.222(PAR) ; also on sheet 113 134
M_E_ACT_N: DIMME1.62(ACT#) DIMME2.62(ACT#) ; also on sheet 127
M_E_ALERT_N: DIMME1.208(ALERT#) DIMME2.208(ALERT#) ; also on sheet 127
M_E_BA_0: DIMME1.81(BA0) DIMME2.81(BA0) ; also on sheet 127
M_E_BA_1: DIMME1.224(BA1) DIMME2.224(BA1) ; also on sheet 127
M_E_BG_0: DIMME1.63(BG0) DIMME2.63(BG0) ; also on sheet 127
M_E_BG_1: DIMME1.207(BG1) DIMME2.207(BG1) ; also on sheet 127
M_E_C_2: DIMME1.235(C2) DIMME2.235(C2) ; also on sheet 127
M_E_CKE_0: DIMME1.60(CKE0) ; also on sheet 127
M_E_CKE_1: DIMME1.203(CKE1) ; also on sheet 127
M_E_CKE_2: DIMME2.60(CKE0) ; also on sheet 127
M_E_CKE_3: DIMME2.203(CKE1) ; also on sheet 127
M_E_CLK_DN_0: DIMME1.75(CK0_DN) ; also on sheet 127
M_E_CLK_DN_1: DIMME2.75(CK0_DN) ; also on sheet 127
M_E_CLK_DN_2: DIMME1.219(CK1_DN) ; also on sheet 127
M_E_CLK_DN_3: DIMME2.219(CK1_DN) ; also on sheet 127
M_E_CLK_DP_0: DIMME1.74(CK0_DP) ; also on sheet 127
M_E_CLK_DP_1: DIMME2.74(CK0_DP) ; also on sheet 127
M_E_CLK_DP_2: DIMME1.218(CK1_DP) ; also on sheet 127
M_E_CLK_DP_3: DIMME2.218(CK1_DP) ; also on sheet 127
M_E_CS_N_0: DIMME1.84(S0#) ; also on sheet 127
M_E_CS_N_1: DIMME1.89(S1#) ; also on sheet 127
M_E_CS_N_2: DIMME1.93(S2_N_C0) ; also on sheet 127
M_E_CS_N_3: DIMME1.237(S3_N_C1) ; also on sheet 127
M_E_CS_N_4: DIMME2.84(S0#) ; also on sheet 127
M_E_CS_N_5: DIMME2.89(S1#) ; also on sheet 127
M_E_CS_N_6: DIMME2.93(S2_N_C0) ; also on sheet 127
M_E_CS_N_7: DIMME2.237(S3_N_C1) ; also on sheet 127
M_E_DQ_0: DIMME1.5(DQ_0) DIMME2.5(DQ_0) ; also on sheet 127
M_E_DQ_1: DIMME1.150(DQ_1) DIMME2.150(DQ_1) ; also on sheet 127
M_E_DQ_2: DIMME1.12(DQ_2) DIMME2.12(DQ_2) ; also on sheet 127
M_E_DQ_3: DIMME1.157(DQ_3) DIMME2.157(DQ_3) ; also on sheet 127
M_E_DQ_4: DIMME1.3(DQ_4) DIMME2.3(DQ_4) ; also on sheet 127
M_E_DQ_5: DIMME1.148(DQ_5) DIMME2.148(DQ_5) ; also on sheet 127
M_E_DQ_6: DIMME1.10(DQ_6) DIMME2.10(DQ_6) ; also on sheet 127
M_E_DQ_7: DIMME1.155(DQ_7) DIMME2.155(DQ_7) ; also on sheet 127
M_E_DQ_8: DIMME1.16(DQ_8) DIMME2.16(DQ_8) ; also on sheet 127
M_E_DQ_9: DIMME1.161(DQ_9) DIMME2.161(DQ_9) ; also on sheet 127
M_E_DQ_10: DIMME1.23(DQ_10) DIMME2.23(DQ_10) ; also on sheet 127
M_E_DQ_11: DIMME1.168(DQ_11) DIMME2.168(DQ_11) ; also on sheet 127
M_E_DQ_12: DIMME1.14(DQ_12) DIMME2.14(DQ_12) ; also on sheet 127
M_E_DQ_13: DIMME1.159(DQ_13) DIMME2.159(DQ_13) ; also on sheet 127
M_E_DQ_14: DIMME1.21(DQ_14) DIMME2.21(DQ_14) ; also on sheet 127
M_E_DQ_15: DIMME1.166(DQ_15) DIMME2.166(DQ_15) ; also on sheet 127
M_E_DQ_16: DIMME1.27(DQ_16) DIMME2.27(DQ_16) ; also on sheet 127
M_E_DQ_17: DIMME1.172(DQ_17) DIMME2.172(DQ_17) ; also on sheet 127
M_E_DQ_18: DIMME1.34(DQ_18) DIMME2.34(DQ_18) ; also on sheet 127
M_E_DQ_19: DIMME1.179(DQ_19) DIMME2.179(DQ_19) ; also on sheet 127
M_E_DQ_20: DIMME1.25(DQ_20) DIMME2.25(DQ_20) ; also on sheet 127
M_E_DQ_21: DIMME1.170(DQ_21) DIMME2.170(DQ_21) ; also on sheet 127
M_E_DQ_22: DIMME1.32(DQ_22) DIMME2.32(DQ_22) ; also on sheet 127
M_E_DQ_23: DIMME1.177(DQ_23) DIMME2.177(DQ_23) ; also on sheet 127
M_E_DQ_24: DIMME1.38(DQ_24) DIMME2.38(DQ_24) ; also on sheet 127
M_E_DQ_25: DIMME1.183(DQ_25) DIMME2.183(DQ_25) ; also on sheet 127
M_E_DQ_26: DIMME1.45(DQ_26) DIMME2.45(DQ_26) ; also on sheet 127
M_E_DQ_27: DIMME1.190(DQ_27) DIMME2.190(DQ_27) ; also on sheet 127
M_E_DQ_28: DIMME1.36(DQ_28) DIMME2.36(DQ_28) ; also on sheet 127
M_E_DQ_29: DIMME1.181(DQ_29) DIMME2.181(DQ_29) ; also on sheet 127
M_E_DQ_30: DIMME1.43(DQ_30) DIMME2.43(DQ_30) ; also on sheet 127
M_E_DQ_31: DIMME1.188(DQ_31) DIMME2.188(DQ_31) ; also on sheet 127
M_E_DQ_32: DIMME1.97(DQ_32) DIMME2.97(DQ_32) ; also on sheet 127
M_E_DQ_33: DIMME1.242(DQ_33) DIMME2.242(DQ_33) ; also on sheet 127
M_E_DQ_34: DIMME1.104(DQ_34) DIMME2.104(DQ_34) ; also on sheet 127
M_E_DQ_35: DIMME1.249(DQ_35) DIMME2.249(DQ_35) ; also on sheet 127
M_E_DQ_36: DIMME1.95(DQ_36) DIMME2.95(DQ_36) ; also on sheet 127
M_E_DQ_37: DIMME1.240(DQ_37) DIMME2.240(DQ_37) ; also on sheet 127
M_E_DQ_38: DIMME1.102(DQ_38) DIMME2.102(DQ_38) ; also on sheet 127
M_E_DQ_39: DIMME1.247(DQ_39) DIMME2.247(DQ_39) ; also on sheet 127
M_E_DQ_40: DIMME1.108(DQ_40) DIMME2.108(DQ_40) ; also on sheet 127
M_E_DQ_41: DIMME1.253(DQ_41) DIMME2.253(DQ_41) ; also on sheet 127
M_E_DQ_42: DIMME1.115(DQ_42) DIMME2.115(DQ_42) ; also on sheet 127
M_E_DQ_43: DIMME1.260(DQ_43) DIMME2.260(DQ_43) ; also on sheet 127
M_E_DQ_44: DIMME1.106(DQ_44) DIMME2.106(DQ_44) ; also on sheet 127
M_E_DQ_45: DIMME1.251(DQ_45) DIMME2.251(DQ_45) ; also on sheet 127
M_E_DQ_46: DIMME1.113(DQ_46) DIMME2.113(DQ_46) ; also on sheet 127
M_E_DQ_47: DIMME1.258(DQ_47) DIMME2.258(DQ_47) ; also on sheet 127
M_E_DQ_48: DIMME1.119(DQ_48) DIMME2.119(DQ_48) ; also on sheet 127
M_E_DQ_49: DIMME1.264(DQ_49) DIMME2.264(DQ_49) ; also on sheet 127
M_E_DQ_50: DIMME1.126(DQ_50) DIMME2.126(DQ_50) ; also on sheet 127
M_E_DQ_51: DIMME1.271(DQ_51) DIMME2.271(DQ_51) ; also on sheet 127
M_E_DQ_52: DIMME1.117(DQ_52) DIMME2.117(DQ_52) ; also on sheet 127
M_E_DQ_53: DIMME1.262(DQ_53) DIMME2.262(DQ_53) ; also on sheet 127
M_E_DQ_54: DIMME1.124(DQ_54) DIMME2.124(DQ_54) ; also on sheet 127
M_E_DQ_55: DIMME1.269(DQ_55) DIMME2.269(DQ_55) ; also on sheet 127
M_E_DQ_56: DIMME1.130(DQ_56) DIMME2.130(DQ_56) ; also on sheet 127
M_E_DQ_57: DIMME1.275(DQ_57) DIMME2.275(DQ_57) ; also on sheet 127
M_E_DQ_58: DIMME1.137(DQ_58) DIMME2.137(DQ_58) ; also on sheet 127
M_E_DQ_59: DIMME1.282(DQ_59) DIMME2.282(DQ_59) ; also on sheet 127
M_E_DQ_60: DIMME1.128(DQ_60) DIMME2.128(DQ_60) ; also on sheet 127
M_E_DQ_61: DIMME1.273(DQ_61) DIMME2.273(DQ_61) ; also on sheet 127
M_E_DQ_62: DIMME1.135(DQ_62) DIMME2.135(DQ_62) ; also on sheet 127
M_E_DQ_63: DIMME1.280(DQ_63) DIMME2.280(DQ_63) ; also on sheet 127
M_E_DQS_DN_0: DIMME1.152(DQS0_DN) DIMME2.152(DQS0_DN) ; also on sheet 127
M_E_DQS_DN_1: DIMME1.163(DQS1_DN) DIMME2.163(DQS1_DN) ; also on sheet 127
M_E_DQS_DN_2: DIMME1.174(DQS2_DN) DIMME2.174(DQS2_DN) ; also on sheet 127
M_E_DQS_DN_3: DIMME1.185(DQS3_DN) DIMME2.185(DQS3_DN) ; also on sheet 127
M_E_DQS_DN_4: DIMME1.244(DQS4_DN) DIMME2.244(DQS4_DN) ; also on sheet 127
M_E_DQS_DN_5: DIMME1.255(DQS5_DN) DIMME2.255(DQS5_DN) ; also on sheet 127
M_E_DQS_DN_6: DIMME1.266(DQS6_DN) DIMME2.266(DQS6_DN) ; also on sheet 127
M_E_DQS_DN_7: DIMME1.277(DQS7_DN) DIMME2.277(DQS7_DN) ; also on sheet 127
M_E_DQS_DN_8: DIMME1.196(DQS8_DN) DIMME2.196(DQS8_DN) ; also on sheet 127
M_E_DQS_DN_9: DIMME1.8(DQS9_DN) DIMME2.8(DQS9_DN) ; also on sheet 127
M_E_DQS_DN_10: DIMME1.19(DQS10_DN) DIMME2.19(DQS10_DN) ; also on sheet 127
M_E_DQS_DN_11: DIMME1.30(DQS11_DN) DIMME2.30(DQS11_DN) ; also on sheet 127
M_E_DQS_DN_12: DIMME1.41(DQS12_DN) DIMME2.41(DQS12_DN) ; also on sheet 127
M_E_DQS_DN_13: DIMME1.100(DQS13_DN) DIMME2.100(DQS13_DN) ; also on sheet 127
M_E_DQS_DN_14: DIMME1.111(DQS14_DN) DIMME2.111(DQS14_DN) ; also on sheet 127
M_E_DQS_DN_15: DIMME1.122(DQS15_DN) DIMME2.122(DQS15_DN) ; also on sheet 127
M_E_DQS_DN_16: DIMME1.133(DQS16_DN) DIMME2.133(DQS16_DN) ; also on sheet 127
M_E_DQS_DN_17: DIMME1.52(DQS17_DN) DIMME2.52(DQS17_DN) ; also on sheet 127
M_E_DQS_DP_0: DIMME1.153(DQS0_DP) DIMME2.153(DQS0_DP) ; also on sheet 127
M_E_DQS_DP_1: DIMME1.164(DQS1_DP) DIMME2.164(DQS1_DP) ; also on sheet 127
M_E_DQS_DP_2: DIMME1.175(DQS2_DP) DIMME2.175(DQS2_DP) ; also on sheet 127
M_E_DQS_DP_3: DIMME1.186(DQS3_DP) DIMME2.186(DQS3_DP) ; also on sheet 127
M_E_DQS_DP_4: DIMME1.245(DQS4_DP) DIMME2.245(DQS4_DP) ; also on sheet 127
M_E_DQS_DP_5: DIMME1.256(DQS5_DP) DIMME2.256(DQS5_DP) ; also on sheet 127
M_E_DQS_DP_6: DIMME1.267(DQS6_DP) DIMME2.267(DQS6_DP) ; also on sheet 127
M_E_DQS_DP_7: DIMME1.278(DQS7_DP) DIMME2.278(DQS7_DP) ; also on sheet 127
M_E_DQS_DP_8: DIMME1.197(DQS8_DP) DIMME2.197(DQS8_DP) ; also on sheet 127
M_E_DQS_DP_9: DIMME1.7(DQS9_DP) DIMME2.7(DQS9_DP) ; also on sheet 127
M_E_DQS_DP_10: DIMME1.18(DQS10_DP) DIMME2.18(DQS10_DP) ; also on sheet 127
M_E_DQS_DP_11: DIMME1.29(DQS11_DP) DIMME2.29(DQS11_DP) ; also on sheet 127
M_E_DQS_DP_12: DIMME1.40(DQS12_DP) DIMME2.40(DQS12_DP) ; also on sheet 127
M_E_DQS_DP_13: DIMME1.99(DQS13_DP) DIMME2.99(DQS13_DP) ; also on sheet 127
M_E_DQS_DP_14: DIMME1.110(DQS14_DP) DIMME2.110(DQS14_DP) ; also on sheet 127
M_E_DQS_DP_15: DIMME1.121(DQS15_DP) DIMME2.121(DQS15_DP) ; also on sheet 127
M_E_DQS_DP_16: DIMME1.132(DQS16_DP) DIMME2.132(DQS16_DP) ; also on sheet 127
M_E_DQS_DP_17: DIMME1.51(DQS17_DP) DIMME2.51(DQS17_DP) ; also on sheet 127
M_E_ECC_0: DIMME1.49(CB0) DIMME2.49(CB0) ; also on sheet 127
M_E_ECC_1: DIMME1.194(CB1) DIMME2.194(CB1) ; also on sheet 127
M_E_ECC_2: DIMME1.56(CB2) DIMME2.56(CB2) ; also on sheet 127
M_E_ECC_3: DIMME1.201(CB3) DIMME2.201(CB3) ; also on sheet 127
M_E_ECC_4: DIMME1.47(CB4) DIMME2.47(CB4) ; also on sheet 127
M_E_ECC_5: DIMME1.192(CB5) DIMME2.192(CB5) ; also on sheet 127
M_E_ECC_6: DIMME1.54(CB6) DIMME2.54(CB6) ; also on sheet 127
M_E_ECC_7: DIMME1.199(CB7) DIMME2.199(CB7) ; also on sheet 127
M_E_MA_0: DIMME1.79(A0) DIMME2.79(A0) ; also on sheet 127
M_E_MA_1: DIMME1.72(A1) DIMME2.72(A1) ; also on sheet 127
M_E_MA_2: DIMME1.216(A2) DIMME2.216(A2) ; also on sheet 127
M_E_MA_3: DIMME1.71(A3) DIMME2.71(A3) ; also on sheet 127
M_E_MA_4: DIMME1.214(A4) DIMME2.214(A4) ; also on sheet 127
M_E_MA_5: DIMME1.213(A5) DIMME2.213(A5) ; also on sheet 127
M_E_MA_6: DIMME1.69(A6) DIMME2.69(A6) ; also on sheet 127
M_E_MA_7: DIMME1.211(A7) DIMME2.211(A7) ; also on sheet 127
M_E_MA_8: DIMME1.68(A8) DIMME2.68(A8) ; also on sheet 127
M_E_MA_9: DIMME1.66(A9) DIMME2.66(A9) ; also on sheet 127
M_E_MA_10: DIMME1.225(A10) DIMME2.225(A10) ; also on sheet 127
M_E_MA_11: DIMME1.210(A11) DIMME2.210(A11) ; also on sheet 127
M_E_MA_12: DIMME1.65(A12) DIMME2.65(A12) ; also on sheet 127
M_E_MA_13: DIMME1.232(A13) DIMME2.232(A13) ; also on sheet 127
M_E_MA_14: DIMME1.228(A14/WE#) DIMME2.228(A14/WE#) ; also on sheet 127
M_E_MA_15: DIMME1.86(A15/CAS#) DIMME2.86(A15/CAS#) ; also on sheet 127
M_E_MA_16: DIMME1.82(A16/RAS#) DIMME2.82(A16/RAS#) ; also on sheet 127
M_E_MA_17: DIMME1.234(A17) DIMME2.234(A17) ; also on sheet 127
M_E_ODT_0: DIMME1.87(ODT0) ; also on sheet 127
M_E_ODT_1: DIMME1.91(ODT1) ; also on sheet 127
M_E_ODT_2: DIMME2.87(ODT0) ; also on sheet 127
M_E_ODT_3: DIMME2.91(ODT1) ; also on sheet 127
M_E_PAR: DIMME1.222(PAR) DIMME2.222(PAR) ; also on sheet 127
M_EF_RESET_N: DIMME1.58(RESET#) DIMME2.58(RESET#) ; also on sheet 108 109 129
M_EF_VREF: C875.1 C876.1 DIMME1.146(VREFCA) DIMME2.146(VREFCA) ; also on sheet 108 109 129
NV_SAVE_CHD_DIMM1: DIMMD2.230(RFU_2) ; also on sheet 52
NV_SAVE_CHE_DIMM0: DIMME1.230(RFU_2) ; also on sheet 52
NV_SAVE_CHE_DIMM1: DIMME2.230(RFU_2) ; also on sheet 52
PVPP_CD: DIMMD2.139(SA0) DIMMD2.142(VPP_0) DIMMD2.143(VPP_1) DIMMD2.238(SA2) DIMMD2.284(VDDSPD) DIMMD2.286(VPP_2) DIMMD2.287(VPP_3) DIMMD2.288(VPP_4) ; also on sheet 22 113 114 115 160
PVPP_EF: DIMME1.142(VPP_0) DIMME1.143(VPP_1) DIMME1.284(VDDSPD) DIMME1.286(VPP_2) DIMME1.287(VPP_3) DIMME1.288(VPP_4) DIMME2.139(SA0) DIMME2.142(VPP_0) DIMME2.143(VPP_1) DIMME2.284(VDDSPD) DIMME2.286(VPP_2) DIMME2.287(VPP_3) DIMME2.288(VPP_4) ; also on sheet 17 108 109 160
PVTT_CD: DIMMD2.77(VTT_0) DIMMD2.221(VTT_1) ; also on sheet 24 113 114 115
PVTT_EF: DIMME1.77(VTT_0) DIMME1.221(VTT_1) DIMME2.77(VTT_0) DIMME2.221(VTT_1) ; also on sheet 19 108 109
SMB_DDR_CD_SCL_LVC2V5: DIMMD2.141(SCL) ; also on sheet 113 114 115 160
SMB_DDR_CD_SDA_LVC2V5: DIMMD2.285(SDA) ; also on sheet 113 114 115 160
SMB_DDR_EF_SCL_LVC2V5: DIMME1.141(SCL) DIMME2.141(SCL) ; also on sheet 108 109 160
SMB_DDR_EF_SDA_LVC2V5: DIMME1.285(SDA) DIMME2.285(SDA) ; also on sheet 108 109 160

Not connected (* = marked no-connect by the designer): DIMMD2 144(RFU_3)* 205(RFU_0)* 227(RFU_1)* NP1* NP2* NP3*; DIMME1 144(RFU_3)* 205(RFU_0)* 227(RFU_1)* NP1* NP2* NP3*; DIMME2 144(RFU_3)* 205(RFU_0)* 227(RFU_1)* NP1* NP2* NP3*

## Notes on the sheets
sheet 110
- DDR4 DIMM CPU1 CHE-2
- FAB1 REV021 20150424
- FAB1 REV003 20150318
- DIMME2
- I2C Address = A2
- Chip Select Signal DIMM Mapping
- ODT Signal DIMM Mapping
- CKE Signal DIMM Mapping
- DDR4 Clock Signal DIMM Pin Mapping (UDIMM/RDIMM support)
- DIMM
- DIMM Pin
- CPU Signal
- DIMM
- DIMM Pin
- CPU Signal
- DIMM
- DIMM Pin
- CPU Signal
- DIMM
- DIMM Pin
- CPU Signal
- DIMM0
- 83
- CS_N0
- DIMM0
- 86
- ODT0
- DIMM0
- 59
- CKE0
- DIMM0
- 73
- CLK_DP0
- DIMM0
- 88
- CS_N1
- DIMM0
- 90
- ODT1
- DIMM0
- 200
- CKE1
- DIMM0
- 74
- CLK_DN0
- DIMM0
- 92
- CS_N2/C[0]
- DIMM1
- 86
- ODT2
- DIMM1
- 59
- CKE2
- DIMM0
- 215
- CLK_DP2
- DIMM0
- 234
- CS_N3/C[1]
- DIMM1
- 90
- ODT3
- DIMM1
- 200
- CKE3
- DIMM0
- 216
- CLK_DN2
- DIMM1
- 83
- CS_N4
- DIMM1
- 73
- CLK_DP1
- DIMM1
- 88
- CS_N5
- DIMM1
- 74
- CLK_DN1
- DIMM1
- 92
- CS_N6/C[3]
- DIMM1
- 215
- CLK_DP3
- DIMM1
- 234
- CS_N7/C[4]
- DIMM1
- 216
- CLK_DN3
sheet 111
- DDR4 DIMM CPU1 CHE-1
- FAB1 REV021 20150424
- FAB1 REV003 20150318
- DIMME1
- I2C Address = A0
- Chip Select Signal DIMM Mapping
- ODT Signal DIMM Mapping
- CKE Signal DIMM Mapping
- DDR4 Clock Signal DIMM Pin Mapping (UDIMM/RDIMM support)
- DIMM
- DIMM Pin
- CPU Signal
- DIMM
- DIMM Pin
- CPU Signal
- DIMM
- DIMM Pin
- CPU Signal
- DIMM
- DIMM Pin
- CPU Signal
- DIMM0
- 83
- CS_N0
- DIMM0
- 86
- ODT0
- DIMM0
- 59
- CKE0
- DIMM0
- 73
- CLK_DP0
- DIMM0
- 88
- CS_N1
- DIMM0
- 90
- ODT1
- DIMM0
- 200
- CKE1
- DIMM0
- 74
- CLK_DN0
- DIMM0
- 92
- CS_N2/C[0]
- DIMM1
- 86
- ODT2
- DIMM1
- 59
- CKE2
- DIMM0
- 215
- CLK_DP2
- DIMM0
- 234
- CS_N3/C[1]
- DIMM1
- 90
- ODT3
- DIMM1
- 200
- CKE3
- DIMM0
- 216
- CLK_DN2
- DIMM1
- 83
- CS_N4
- DIMM1
- 73
- CLK_DP1
- DIMM1
- 88
- CS_N5
- DIMM1
- 74
- CLK_DN1
- DIMM1
- 92
- CS_N6/C[3]
- DIMM1
- 215
- CLK_DP3
- DIMM1
- 234
- CS_N7/C[4]
- DIMM1
- 216
- CLK_DN3
sheet 112
- DDR4 DIMM CPU0 CHD-2
- FAB1 REV021 20150424
- FAB1 REV003 20150318
- DIMMD2
- I2C Address = AA
- Chip Select Signal DIMM Mapping
- ODT Signal DIMM Mapping
- CKE Signal DIMM Mapping
- DDR4 Clock Signal DIMM Pin Mapping (UDIMM/RDIMM support)
- DIMM
- DIMM Pin
- CPU Signal
- DIMM
- DIMM Pin
- CPU Signal
- DIMM
- DIMM Pin
- CPU Signal
- DIMM
- DIMM Pin
- CPU Signal
- DIMM0
- 83
- CS_N0
- DIMM0
- 86
- ODT0
- DIMM0
- 59
- CKE0
- DIMM0
- 73
- CLK_DP0
- DIMM0
- 88
- CS_N1
- DIMM0
- 90
- ODT1
- DIMM0
- 200
- CKE1
- DIMM0
- 74
- CLK_DN0
- DIMM0
- 92
- CS_N2/C[0]
- DIMM1
- 86
- ODT2
- DIMM1
- 59
- CKE2
- DIMM0
- 215
- CLK_DP2
- DIMM0
- 234
- CS_N3/C[1]
- DIMM1
- 90
- ODT3
- DIMM1
- 200
- CKE3
- DIMM0
- 216
- CLK_DN2
- DIMM1
- 83
- CS_N4
- DIMM1
- 73
- CLK_DP1
- DIMM1
- 88
- CS_N5
- DIMM1
- 74
- CLK_DN1
- DIMM1
- 92
- CS_N6/C[3]
- DIMM1
- 215
- CLK_DP3
- DIMM1
- 234
- CS_N7/C[4]
- DIMM1
- 216
- CLK_DN3
